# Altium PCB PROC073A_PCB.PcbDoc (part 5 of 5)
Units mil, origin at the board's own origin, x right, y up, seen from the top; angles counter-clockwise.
Board outline 2165.35 x 2165.35 mil, 6 copper layers (Top Layer, L2, L3, L4, L5, Bottom Layer), stack 55.77 mil thick; 284 components, 233 nets, 945 pads, 1419 vias.
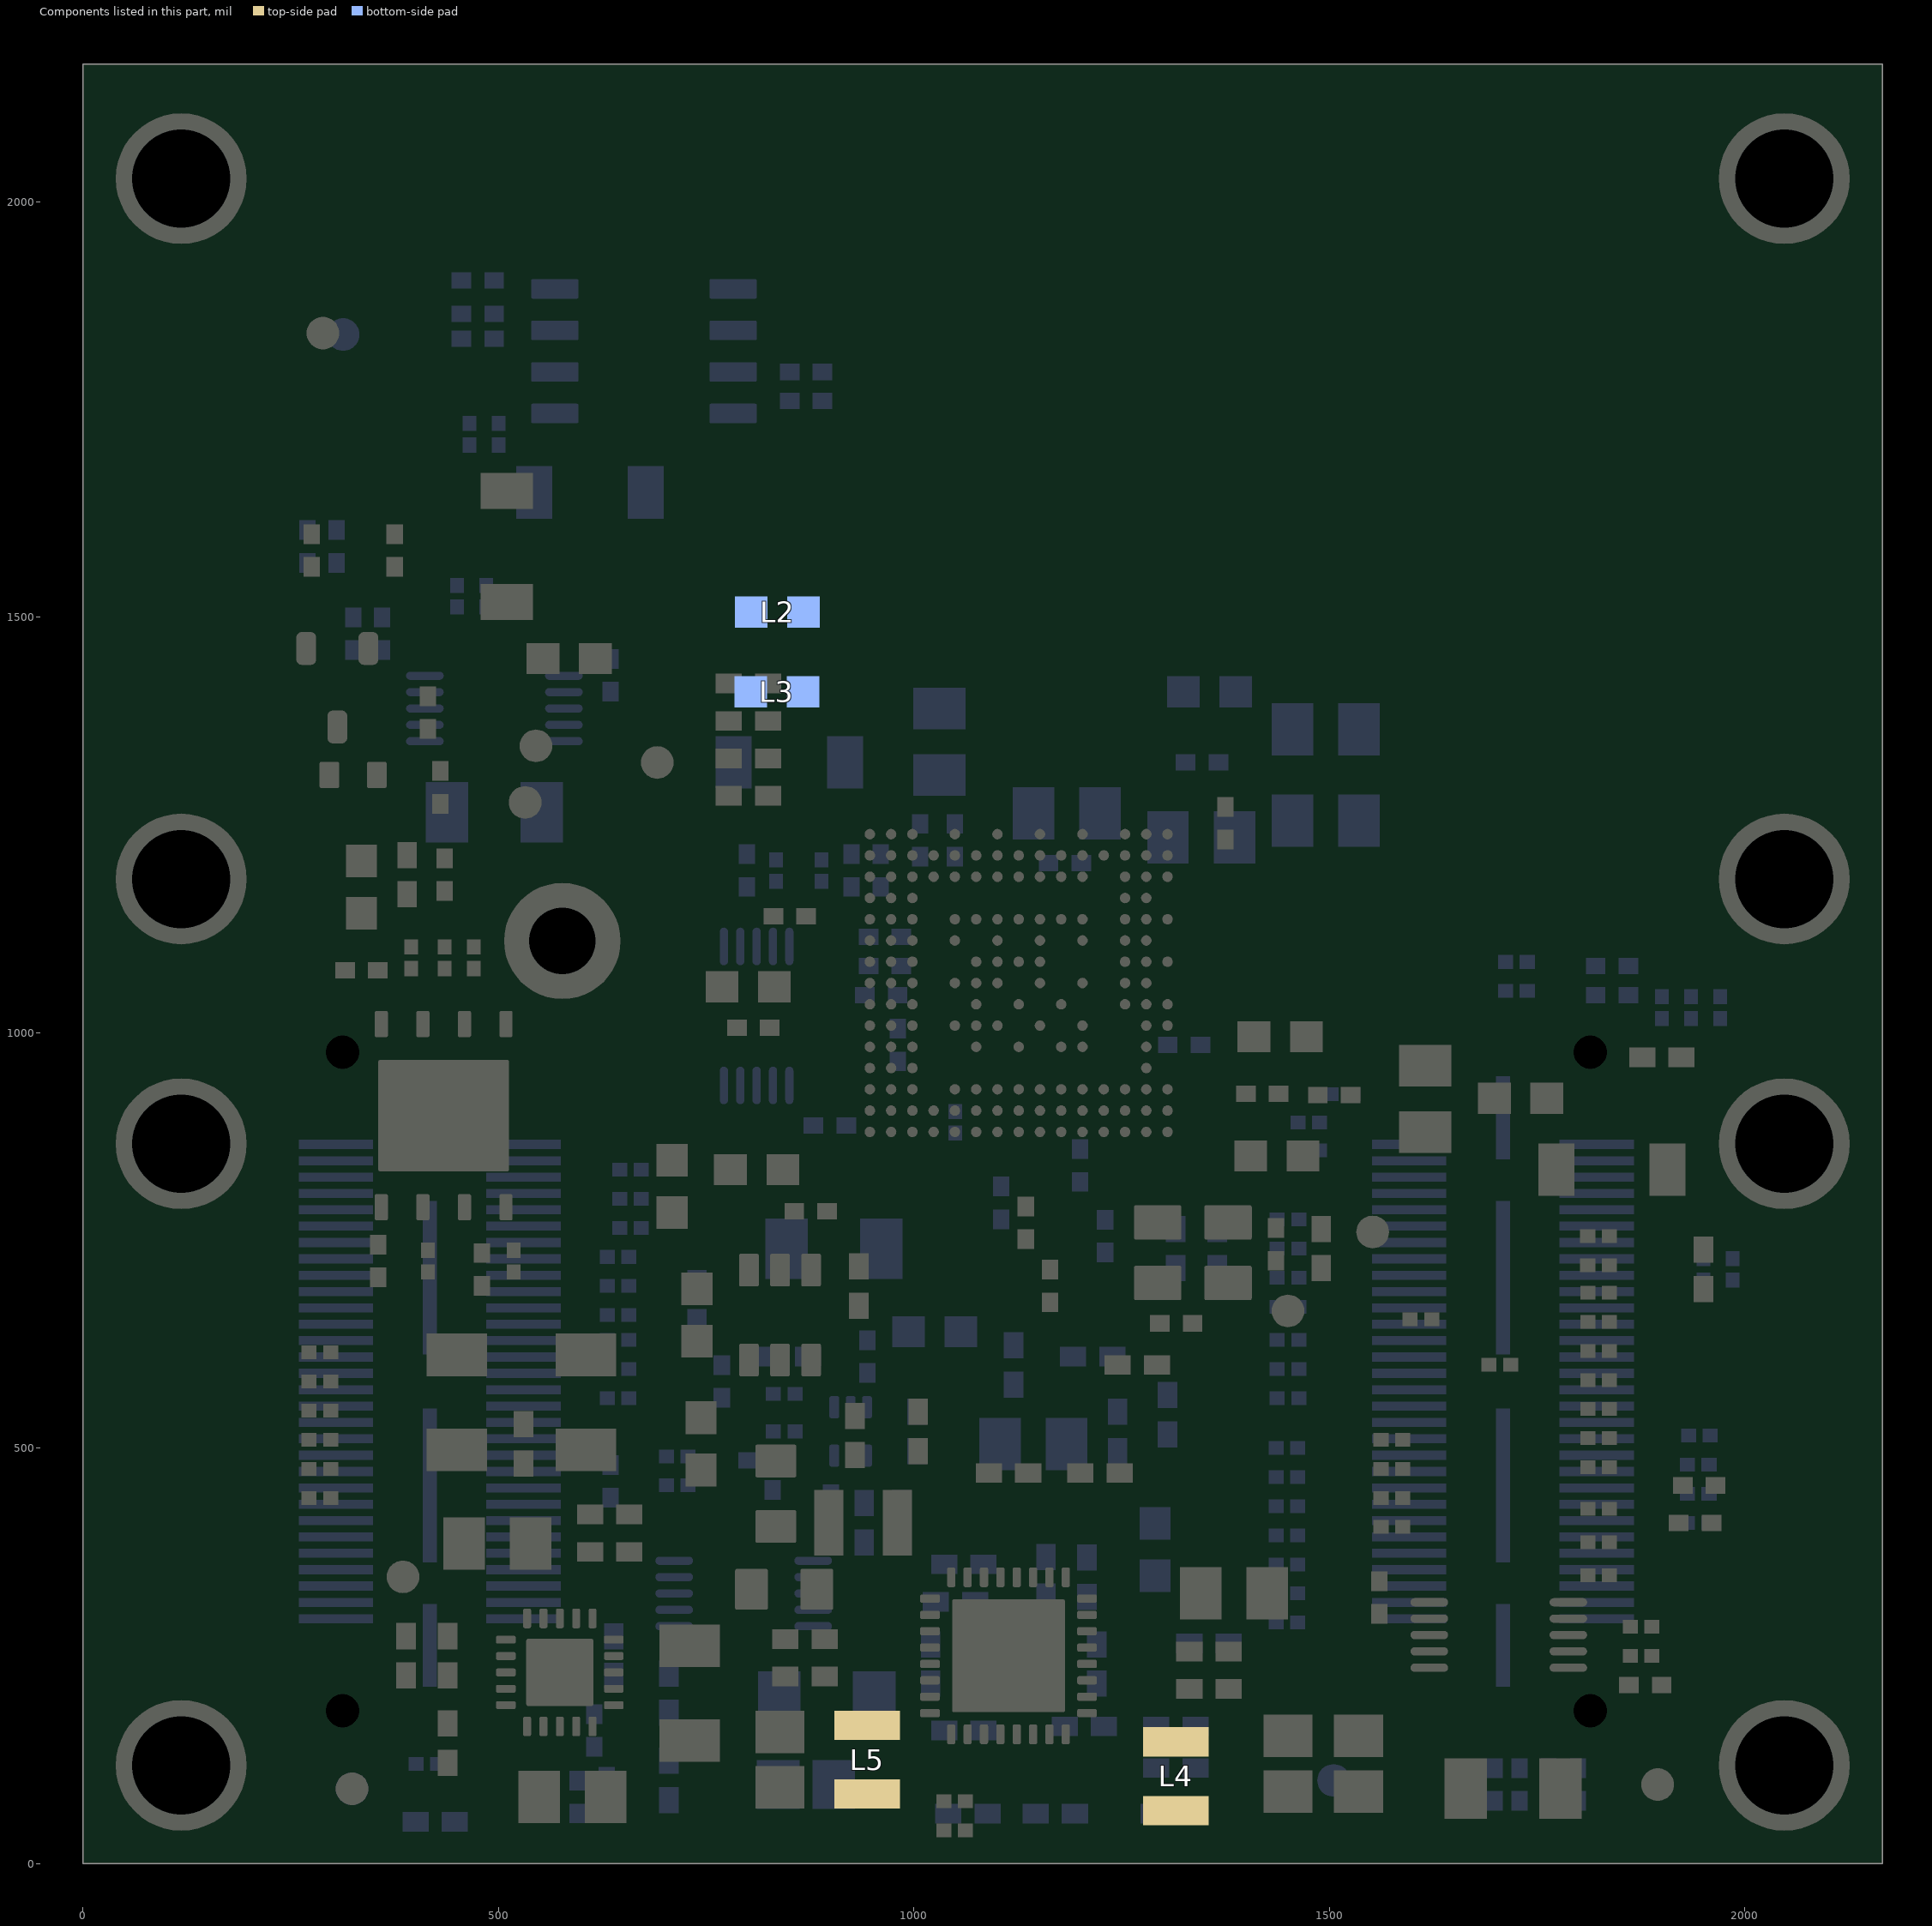
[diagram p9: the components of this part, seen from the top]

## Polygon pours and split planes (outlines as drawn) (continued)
GND on Bottom Layer "TOP-No Net 1" (solid, remove dead copper, pour order 388): 40 vertices, not listed, extent 1067,966 2136,1966
no net on Bottom Solder "RADAR_1V8_L01_P-001" (solid): 34 vertices, not listed, extent 1068,974 1955,2010.87
no net on Top Solder "Top Solder-No Net" (solid): 91 vertices, not listed, extent 801.83,1018 1994,2144
GND on L5 "TOP-No Net 1" (solid, remove dead copper, pour order 376): 32.89,2147.39 2147.89,2147.38 2147.89,23.38 32.89,23.38
GND on L2 "GND_L02_P226" (hatched 90Degree grid 5 track 8, remove dead copper, pour order 226): 35,2140 2135.01,2140 2135,25 34.99,25

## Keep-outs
L2:
  circle w1: c1074.8,1213.16 r7.87
  circle w1: c1177.16,1213.16 r7.87
  circle w1: c1125.98,1213.16 r7.87
  circle w1: c1279.52,1059.62 r7.87
  circle w1: c1279.52,1161.98 r7.87
  circle w1: c1279.52,1110.8 r7.87
  circle w1: c312.12,976.26 r32
  circle w1: c1023.62,1213.16 r7.87
L3:
  circle w1: c312.12,976.26 r32
L4:
  circle w1: c312.12,976.26 r32
L5:
  circle w1: c312.12,976.26 r32
Bottom Layer:
  circle w1: c312.12,976.26 r27.7
Keep-Out Layer:
  circle w1: c1813.86,976.26 r32
  circle w1: c1813.86,183.74 r31
  circle w1: c312.12,183.74 r32
  lines w10: 0,0 0,2165.35 2165.35,2165.35 2165.35,0 0,0
  text ".Layer_Name" at -423,-1858.49 h60

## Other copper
Top Layer:
  pour cut-out: 1039.36,1213.16 cw(c1023.62,1213.16) 1023.62,1197.42 cw(c1023.62,1213.16) 1007.88,1213.16 cw(c1023.62,1213.16) 1023.62,1228.9 cw(c1023.62,1213.16)
  pour cut-out: 1090.54,1213.16 cw(c1074.8,1213.16) 1074.8,1197.42 cw(c1074.8,1213.16) 1059.06,1213.16 cw(c1074.8,1213.16) 1074.8,1228.9 cw(c1074.8,1213.16)
  pour cut-out: 1141.72,1213.16 cw(c1125.98,1213.16) 1125.98,1197.42 cw(c1125.98,1213.16) 1110.24,1213.16 cw(c1125.98,1213.16) 1125.98,1228.9 cw(c1125.98,1213.16)
  pour cut-out: 1192.9,1213.16 cw(c1177.16,1213.16) 1177.16,1197.42 cw(c1177.16,1213.16) 1161.42,1213.16 cw(c1177.16,1213.16) 1177.16,1228.9 cw(c1177.16,1213.16)
  pour cut-out: 1295.26,1161.98 cw(c1279.52,1161.98) 1279.52,1146.24 cw(c1279.52,1161.98) 1263.78,1161.98 cw(c1279.52,1161.98) 1279.52,1177.72 cw(c1279.52,1161.98)
  pour cut-out: 1295.26,1110.8 cw(c1279.52,1110.8) 1279.52,1095.06 cw(c1279.52,1110.8) 1263.78,1110.8 cw(c1279.52,1110.8) 1279.52,1126.54 cw(c1279.52,1110.8)
  pour cut-out: 1295.26,1059.62 cw(c1279.52,1059.62) 1279.52,1043.88 cw(c1279.52,1059.62) 1263.78,1059.62 cw(c1279.52,1059.62) 1279.52,1075.36 cw(c1279.52,1059.62)
  text ".Layer_Name" at -423,-1858.49 h60
L2:
  pour cut-out: 1266.57,249.91 1266.57,264.58 1268.2,266.21 1277.24,266.21 1281.41,262.04 1281.41,246.12 1269.64,246.12 1266.57,249.19 1266.39,249.19
  pour cut-out: 1733.71,281.38 1733.71,296.05 1735.34,297.68 1744.38,297.68 1748.55,293.51 1748.55,277.59 1736.78,277.59 1733.71,280.66 1733.53,280.66
  pour cut-out: 1267.4,288.87 1267.4,303.54 1269.03,305.17 1278.07,305.17 1282.24,301 1282.24,285.08 1270.47,285.08 1267.4,288.15 1267.22,288.15
  pour cut-out: 1366.38,480.03 1381.05,480.03 1382.68,478.4 1382.68,469.36 1378.51,465.19 1362.59,465.19 1362.59,476.96 1365.66,480.03 1365.66,480.21
  pour cut-out: 2140.93,1364.44 1997.92,1364.44 1885.11,1251.63 1885.11,1223.22 1682.7,1020.81 1621.63,1020.81 1392.37,1020.81 1354.68,983.12 1354.68,905.79 1354.68,819.37 1374.9,819.37 1374.9,930.19 1374.9,972.62 1400.28,998 1691.88,998 1908.35,1214.47 1908.35,1239.56 2011.45,1342.66 2140.93,1342.66
  pour cut-out: 1236.78,839.76 1245.87,848.86 1245.87,861.13 1075.37,1031.63 1075.37,1053.79 1033,1096.16 1033,1145.42 1014.95,1163.47 977.13,1201.29 977.13,1273.51 809.63,1441.01 809.63,2144.85 788,2144.85 788,1430.4 956.28,1262.12 956.28,1189.05 1012.83,1132.5 1012.83,1082.88 1057.82,1037.89 1057.82,1018.72
  pour cut-out: 1250,823 1236,809 1236,680 1257,659 1257,621 1263,615 1320,615 1344,639 1403,639 1411,647 1411,672 1433,694 1462,694 1470,702 1470,779 1435,814 1373,814 1373,833 1454.66,833 1486.15,801.5 1486.15,697.29 1465.09,676.23 1444.23,676.23 1426,658 1426,650 1397,621 1354.51,621.01 1329.44,595.94 1257.05,595.94 1236.03,616.97 1236.02,657.78 1216.02,677.8 1216.02,819 1230.01,832.99 1249.76,833
  pour cut-out: 1218.81,673.89 1218.81,658.1 1213.48,652.77 1221.37,644.88 1227.89,644.88 1227.89,650.21 1236.96,659.29 1224.73,671.52 1224.73,673.3
  pour cut-out: 1029,1161 1044,1161 1044,1145.76 1041.24,1143 1023,1143 1023,1155
  pour cut-out: 1060,977.16 1075,977.16 1075,961.93 1072.23,959.16 1054,959.16 1054,971.16
  pour cut-out: 1085.74,975.16 1100.74,975.16 1100.74,959.93 1097.97,957.16 1079.74,957.16 1079.74,969.16
  pour cut-out: 1255,995.16 1270,995.16 1270,979.93 1267.23,977.16 1249,977.16 1249,989.16
  pour cut-out: 1023.84,1035.75 1023.84,1050.75 1039.07,1050.75 1041.84,1047.98 1041.84,1029.75 1029.84,1029.75
  pour cut-out: 1031,1101.16 1046,1101.16 1046,1085.93 1043.23,1083.16 1025,1083.16 1025,1095.16
  pour cut-out: 885,1031.35 900,1031.35 900,1016.11 897.23,1013.35 879,1013.35 879,1025.35
  pour cut-out: 1158.84,1148 1158.84,1163 1174.07,1163 1176.84,1160.23 1176.84,1142 1164.84,1142
  pour cut-out: 1031.49,1213.16 cw(c1023.62,1213.16) 1023.62,1205.29 cw(c1023.62,1213.16) 1015.75,1213.16 cw(c1023.62,1213.16) 1023.62,1221.03 cw(c1023.62,1213.16)
  pour cut-out: 1031.49,1213.16 cw(c1023.62,1213.16) 1023.62,1205.29 cw(c1023.62,1213.16) 1015.75,1213.16 cw(c1023.62,1213.16) 1023.62,1221.03 cw(c1023.62,1213.16)
  text "Layer 2 - GND1" at -403.92,-1847.45 h60
L3:
  pour cut-out: 1267.67,271.41 1276.33,271.41 1287.55,260.19 1287.55,255.38 1277.61,245.44 1266.39,245.44 1261.58,250.25 1261.58,264.68 1267.03,270.13
  pour cut-out: 1180.53,1165.47 1183,1163 1178.14,1158.14 1178.14,1144.86 1173.94,1140.67 1154.33,1140.67 1146.87,1148.13 1146.87,1154.07 1158.27,1165.47
  text "Layer 3 - Sig1" at -394.11,-1858.93 h60
L4:
  text "Layer 4 - Sig2" at -362.17,-1856.02 h60
L5:
  pour cut-out: 885.48,638.59 885.48,641.16 891.89,647.57 897.35,647.57 906.33,638.59 898.95,631.21 898.95,628.33 895.1,628.33 886.44,636.99
  pour cut-out: 1743.38,408.24 1743.38,410.81 1749.79,417.22 1755.25,417.22 1764.23,408.24 1756.85,400.86 1756.85,397.98 1753,397.98 1744.34,406.64
  pour cut-out: 1273.11,265.63 1275.68,265.63 1282.09,259.22 1282.09,253.76 1273.11,244.78 1265.73,252.16 1262.85,252.16 1262.85,256.01 1271.51,264.67
  pour cut-out: 1048,981.06 1021.98,981.06 1021.98,998.59 1048,998.59
  pour cut-out: 1048.65,1032.26 1022.63,1032.26 1022.63,1049.79 1048.65,1049.79
  pour cut-out: 1022.8,1103.52 1048.81,1103.52 1048.81,1085.98 1022.8,1085.98
  pour cut-out: 1180.98,1144 1154.96,1144 1154.96,1161.54 1180.98,1161.54
  pour cut-out: 1064,979 1080,963 1080,959 1071,950 1068,950 1052,966 1052,973 1059,980 1062,980
  text "Layer 5 - GND2" at -367.98,-1863.28 h60
Bottom Layer:
  pour cut-out: 263,1913 317,1967 880,1967 908,1939 908,1877 893,1862 274,1862 263,1873
  text ".Layer_Name" at -423,-1858.49 h60
Multi-Layer:
  pour cut-out: 30,20.18 2140,20.17 2140,2144 30,2144 29.99,0 0,0 0,2165.36 2165.35,2165.35 2165.35,0.17 29.99,0.18

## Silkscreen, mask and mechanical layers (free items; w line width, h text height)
Top Overlay:
  lines w6: 200,430 200,485 ; 205,655 205,570 ; 220,215 275,215 280,220 355,220 ; 280,740 335,740 ; 390,1055 495,1055 495,1125 ; 504,1056 510,1050 510,1064 504,1058 520,1058 586,992 ; 505,1169 480,1144 449,1144 ; 585,905 695,905 695,980 ; 603.73,1591.72 603.73,1733.73 ; 604.41,1591.72 684.68,1591.72 ; 634.5,1588.26 758.59,1464.17 758.59,1447.76 ; 695.62,1610.39 695.62,1736 ; 745,320 775,320 ; 885,745 898,758 953,758 960,765 ; 1272,660 1220,660 1175,615 ; 1449.13,704.85 1502.04,651.94 1502.04,627.08 ; 1540,30 1430,30 ; 1670.06,367.05 1778.21,367.05 1789.85,355.41 ; 1754.39,630.84 1765.27,630.84 1785.4,650.97 1790.58,650.97 ; 1776.26,518.81 1789.21,505.86 ; 1856.87,621.93 1866.52,621.93 ; 1858.13,546.96 1865.57,554.4 1920.49,554.4 ; 1859.42,577.37 1865.9,583.85 1922.43,583.85 ; 1903.1,257.37 1910.87,265.14 1910.87,283.26 1930.93,303.32 1970.26,303.32 ; 1916.39,197.29 1926.83,197.29 ; 200,485 205,480 195,480 200,485 ; 205,570 215,580 195,580 205,570 ; 335,740 330,745 330,735 335,740 ; 355,220 345,210 345,230 355,220 ; 449,1144 454,1139 454,1149 449,1144 ; 586,992 585,993 586,992 ; 775,320 770,315 770,325 775,320 ; 1175,615 1185,615 1175,625 1175,615 ; 1430,30 1435,25 1435,35 1430,30
  text "IWR6843ISK" at 253,1972 h40
  text "PROC073    REV A" at 411.5,1938.01 h45
  text ".Layer_Name" at -423,-1858.49 h60
Bottom Overlay:
  circle w6: c293.4,1360.46 r30
  circle w6: c667.74,914.51 r30
  circle w6: c696.91,1255.44 r30
  circle w6: c1147.51,1381.97 r30
  lines w6: 230.93,827.43 249.25,845.75 ; 251.5,1675.94 251.5,1629.19 255.51,1625.17 ; 261.52,1325.38 348.31,1325.38 348.31,1253.11 359.85,1241.57 359.85,1201.73 359.85,1189.06 406.41,1189.06 406.41,1035.98 ; 271,130 285,144 368,144 380,132 ; 405,1686 445,1686 ; 570.74,24.05 577.73,24.05 593.5,39.82 ; 618.56,537.27 677.15,537.27 677.71,537.83 677.71,732.95 698.6,753.84 698.6,860.37 638.79,860.37 ; 700.64,418.92 719.75,438.04 ; 722.34,1233.17 734.1,1221.41 775.46,1221.41 ; 735.74,562.54 746.02,562.54 ; 767.46,493.87 781.15,480.18 ; 779.7,1163.82 779.7,1235.01 949.23,1235.01 983.54,1269.33 1073.68,1269.33 1073.68,1198.14 1062.42,1186.87 997.88,1186.87 ; 786,528 798,516 813,516 ; 788.84,619.17 788.84,590.22 806.86,572.2 815.21,572.2 ; 792.72,445.07 810.38,445.07 ; 911.78,1082.13 925.28,1082.13 ; 917.3,320.25 917.3,357.3 ; 921.79,570.11 924.97,573.29 924.97,642.14 ; 948.09,650.49 948.09,664.06 961.8,677.77 999.23,677.77 1019.59,698.13 ; 962.33,115.79 962.33,139.57 ; 1014.23,435.32 1028.9,435.32 ; 1078.15,1437.65 1078.15,1512.5 1299.27,1512.5 1299.27,1451.97 ; 1085.69,1414.62 1258.93,1414.62 ; 1144.82,653.19 1156.77,665.14 ; 1149,232.7 1149,243.96 ; 1232.5,108.6 1232.5,136.8 ; 1247.75,215.77 1259.92,227.94 1302.34,227.94 ; 1259.57,636.59 1259.57,663.34 ; 1269.53,575.07 1275.5,581.04 1275.5,613.87 1282.63,621 ; 1283.6,854.36 1283.6,811.31 1300.66,794.25 ; 1320.27,850.1 1320.27,830.93 1355.24,795.96 ; 1402,689 1413,700 ; 1406.22,396.43 1414.27,396.43 ; 1473.61,250.2 1473.61,267.98 ; 1477.01,476.01 1486.26,485.25 1486.26,502.57 ; 1521,1480 1521,1420 ; 1629.96,52.08 1635.91,58.03 1635.91,45.58 1629.41,52.08 1699.48,52.08 ; 1782.9,52.26 1833.77,52.26 1826.03,60 1826.03,45.17 1833.12,52.26 ; 1864.28,1024.13 1864.28,1001.92 1900.82,965.38 ; 1872.86,294.22 1888.58,278.5 1888.54,236.56 ; 1922.17,770.29 1942.88,749.58 ; 1930.65,540.63 1937.25,547.23 1923.77,547.23 1930.65,540.35 1930.65,591.76 ; 1956.58,770.95 1977.95,749.58 ; 445,1686 440,1691 440,1681 445,1686 ; 1521,1420 1511,1430 1531,1430 1521,1420
  text "TEXAS" at 1026,1608 h70
  text "INSTRUMENTS" at 1111,1548 h70
  text "B" at 1159.27,1365.1 h50
  text "A" at 310.33,1344.76 h50
  text "B" at 708.67,1238.57 h50
  text "A" at 684.67,898.81 h50
  text "5V_IN" at 581.26,877.54 h45 r270
  text "60" at 1945,867 h60
  text "5V_IN" at 220.8,864.76 h50 r270
  text "VPP_1P7" at 219.08,671.37 h40 r270
  text "1V8" at 1546.29,359.69 h40
  text "1V2" at 1546.95,328.54 h40
  text "3V3" at 1939.64,309.24 h40
  text "1V0" at 1545.43,290.64 h40
  text "60" at 248,252 h60
  text "5V_IN" at 1964.35,203.39 h40
  text "1" at 1549.43,167.64 h60
  text ".Layer_Name" at -423,-1858.49 h60
Top Paste:
  text ".Layer_Name" at -423,-1858.49 h60
Bottom Paste:
  text ".Layer_Name" at -423,-1858.49 h60
Top Solder:
  rectangle: 33,2005 900,2144
  region: 30,20.18 214.97,20.18 214.97,190.03 170.99,234.01 170.99,645.99 226.41,701.41 226.41,971.41 226.41,2144 30,2144
  region: 1965,20 2140,20.17 2140,2144 1960,2144 1960,815 2015,760 2015,245 1950,180 1950,30 1960,20
  text ".Layer_Name" at -423,-1858.49 h60
  text ".Layer_Name" at -423,-1858.49 h60
Bottom Solder:
  region: 1965,20 2140,20.17 2140,2144 30,2144 30,20.18 214.94,20.18 215.12,189.87 170,234.99 170,644 205,679 205,1113 241,1149 241,1891.29 335.84,1986.13 1940,1986.13 1940,1219 2019.99,1139 2020,970.99 1962.25,913.25 1962.25,827.4 2015.39,774.26 2015.39,235.39 1950,170 1950,35
  region: 1911.1,1225.53 1937.91,1225.53 2022.09,1141.35 2022.09,1135.02 2021.72,1134.65 1931.58,1134.65 1902.9,1163.33 1902.9,1217.7 1911.1,1225.9
  text ".Layer_Name" at -423,-1858.49 h60
Drill Guide:
  text ".Layer_Name" at -423,-1858.49 h60
M1 Board Outline:
  the board outline again, w8
  text ".Layer_Name" at -423,-1858.49 h60
M2 Board Dimensions:
  rectangle: -1000,-1275 -875,-1150
  rectangle: -875,-1400 -500,-1275
  lines w7: -1000,-1275 0,-1275 ; -875,-1400 -875,-1150 ; -750,-1400 -750,-1150 ; -500,-1400 -500,-1150 ; -250,-1400 -250,-1150 ; -1000,-1400 0,-1400 0,-1150 -1000,-1150 -1000,-1400
M3 3D STEP Top:
  text ".Layer_Name" at -423,-1858.49 h60
M4 3D STEP Bottom:
  text ".Layer_Name" at -423,-1858.49 h60
M5 Assembly Top:
  circle w15: c344,1478 r3
  lines w6: 380,1130 495,1130 495,1050 385,1050 ; 500,1205 595,1205 595,1285 500,1285 ; 535,1205 470,1140 ; 470,1140 480,1140 470,1150 470,1140
  lines w10: -1292,-1930.17 5308,-1930.17 ; -1292,-1726.83 5310,-1726.83 ; -1292,-1523.5 -1292,-2133.5 2713,-2133.5 5310,-2133.5 5310,-1523.5 -1291.5,-1523.5 -1291.5,-2133.5 284,-2133.5 ; 1173,-2133.5 1173,-1523.5 ; 2440,-1726.83 2440,-1523.5 ; 3280,-1726.83 3280,-1523.5 ; 3902,-2140 3902,-1937.17
  text "COMPONENTS MARKED 'DNP' SHOULD NOT BE POPULATED." at 153.5,-1318.5 h60
  text "ASSEMBLY VARIANT:" at 153,-1434 h60
  text ".VariantName" at 1189,-1434 h60
  text "PCB VIEWED FROM TOP SIDE" at -1228.5,-1655.67 h60
  text "BOARD #:" at 1248,-1655.67 h60
  text ".PRJ_Number" at 1793.5,-1655.67 h60
  text "REV:" at 2638,-1655.67 h60
  text ".PCB_Rev" at 2929.5,-1655.67 h60
  text "SVN REV:" at 3476,-1655.67 h60
  text ".VersionControl_RevNumber" at 3982,-1655.67 h60
  text "Assembly Layer Top" at -433,-1855 h60
  text "TID #:" at 1248,-1859 h60
  text ".TID" at 1793.5,-1859 h60
  text "PLOT NAME =" at -1228.5,-2064.34 h60
  text ".plot_File_Name" at -423,-2064.34 h60
  text "GENERATED    :" at 1250,-2064.34 h60
  text ".Print_Date" at 2119.5,-2064.34 h60
  text ".Print_Time" at 2848.5,-2064.34 h60
  text "TEXAS INSTRUMENTS" at 4113,-2064.34 h60
M6 Assembly Bottom:
  lines w6: 705,725 705,865 ; 786.98,637.71 791.01,633.68 791.01,583.68 810.46,564.23 810.46,571.43 802.41,563.38 809.61,563.38 ; 833.84,1230.77 833.84,1248.26 ; 1770.26,1133.61 1770.26,1075.96 1798.64,1047.57 1798.64,1057.45 1788.68,1047.48 1796.09,1047.48 ; 705,865 714.25,855.75 695.75,855.75 705,865
  lines w10: -1292.5,-1727.33 5309.5,-1727.33 ; -1290.5,-1930.67 5309.5,-1930.67 ; 115.5,-2140.5 115.5,-1937.67 ; 737.5,-1727.33 737.5,-1524 ; 1577.5,-1727.33 1577.5,-1524 ; 2844.5,-2134 2844.5,-1524 ; 3733.5,-2134 5309,-2134 5309,-1524 -1292.5,-1524 -1292.5,-2134 1304.5,-2134 5309.5,-2134 5309.5,-1524
  text "2" at 323,868 h45
  text "1" at 532,868 h45
  text "59" at 1636,865.43 h45
  text "60" at 1821.54,865.43 h45
  text "60" at 345,266 h45
  text "59" at 533,266 h45
  text "1" at 1611,265 h45
  text "2" at 1822,265 h45
  text "COMPONENTS MARKED 'DNP' SHOULD NOT BE POPULATED." at 5102,-1318 h60
  text ".VariantName" at 4058,-1434 h60
  text "ASSEMBLY VARIANT:" at 5097,-1434 h60
  text ".VersionControl_RevNumber" at 35.5,-1656.17 h60
  text "SVN REV:" at 541.5,-1656.17 h60
  text ".PCB_Rev" at 1088,-1656.17 h60
  text "REV:" at 1379.5,-1656.17 h60
  text ".PRJ_Number" at 2224,-1656.17 h60
  text "BOARD #:" at 2769.5,-1656.17 h60
  text "PCB VIEWED FROM BOTTOM SIDE" at 5246,-1656.17 h60
  text "Assembly Bottom Layer" at 4885,-1845 h60
  text ".TID" at 2224,-1859.5 h60
  text "TID #:" at 2769.5,-1859.5 h60
  text "TEXAS INSTRUMENTS" at -95.5,-2064.84 h60
  text ".Print_Time" at 1169,-2064.84 h60
  text ".Print_Date" at 1898,-2064.84 h60
  text "GENERATED    :" at 2767.5,-2064.84 h60
  text ".plot_File_Name" at 4440.5,-2064.84 h60
  text "PLOT NAME =" at 5246,-2064.84 h60
M7 LPKF Text Top:
  lines w2: 1007.88,1213.16 1039.36,1213.16 ; 1015.75,1213.16 1031.49,1213.16 ; 1023.62,1197.42 1023.62,1228.9 ; 1023.62,1205.29 1023.62,1221.03
M9 Title Sheet:
  drawing of 57 lines, arcs and shapes, not listed
  text "1" at -260.16,7036.5 h70
  text "2" at 2235.5,7036.5 h70
  text "3" at 4724.84,7036.5 h70
  text "4" at 7231.51,7036.5 h70
  text "5" at 9730.5,7036.5 h70
  text "6" at 12235.5,7036.5 h70
  text "A" at -1416.5,5893.5 h70
  text "A" at 13383.5,5893.5 h70
  text "B" at -1416.5,3513.5 h70
  text "B" at 13383.5,3513.5 h70
  text "C" at -1416.5,1138.5 h70
  text "C" at 13383.5,1138.5 h70
  text "PROJECT TITLE:" at 10343.5,-722.5 h45
  text ".PRJ_Title" at 10393.5,-855.83 h70
  text "DESIGNED FOR:" at 10343.5,-1023.5 h45
  text ".PRJ_Customer" at 10393.5,-1163.5 h70
  text "D" at -1416.5,-1231.5 h70
  text "D" at 13383.5,-1231.5 h70
  text "FILE NAME:" at 10343.5,-1323.5 h45
  text ".PCB_File_Name_No_Path" at 10393.5,-1443.5 h70
  text "Texas Instruments (TI) and/or its licensors do not warrant the accuracy or completeness of this specification" at 5374,-1605.34 h45
  text "ENGINEER:" at 10343.5,-1613.5 h45
  text "LAYOUT BY:" at 11848.5,-1613.5 h45
  text "or any information contained therein. TI and/or its licensors do not warrant that this design will meet" at 5329.01,-1718 h45
  text ".PRJ_Engineer" at 10393.5,-1768.49 h70
  text ".PCB_Layout" at 11899,-1768.49 h70
  text "the specifications, will be suitable for your application or fit for any particular purpose, or will operate in" at 5329.01,-1830.67 h45
  text "ALTIUM DESIGNER VERSION:" at 11848.5,-1923.5 h45
  text "an implementation. TI and/or its licensors do not warrant that the design is production worthy. You should" at 5329.01,-1943.33 h45
  text "completely validate and test your design implementation to confirm the system functionality for your application." at 5374,-2056 h45
  text ".print_Scale" at 10393.5,-2056.83 h70
  text ".Application_BuildNumber" at 11899,-2056.83 h70
  text "1" at -260.16,-2263.5 h70
  text "2" at 2235.5,-2263.5 h70
  text "3" at 4724.84,-2263.5 h70
  text "4" at 7231.51,-2263.5 h70
  text "5" at 9730.5,-2263.5 h70
  text "6" at 12235.5,-2263.5 h70
M10 Fab Notes:
  drawing of 189 lines, arcs and shapes, not listed
  text "DESIGN INFORMATION" at 11382.02,5356.17 h60
  text "MIN. TRACK WIDTH:" at 10737.46,5224.05 h60
  text "4" at 11833.7,5224.05 h60
  text "MIL" at 11988.46,5224.05 h60
  text "MIN. CLEARANCE:" at 10737.46,5099.92 h60
  text "4" at 11773.7,5099.93 h60
  text "MIL" at 11988.46,5099.92 h60
  text "MIN. VIA PAD SIZE:" at 10737.46,4975.8 h60
  text "13.77" at 11679,4971 h60
  text "MIL" at 12011,4967 h60
  text "0.099mm (3.9MIL)" at 11432.46,4845.9 h60
  text "EXTERNAL" at 12194,4842 h60
  text "MINIMUM ANNULAR RING" at 10408.23,4837.67 h60
  text "PER" at 10608.23,4727.55 h60
  text "IPC-D-275 CLASS 2 LEVEL C" at 10828.23,4727.54 h60
  text "MIL, HOLES" at 12316.46,4627.07 h60
  text "+/-" at 11924,4618.48 h60
  text "+/-" at 12778,4618.48 h60
  text "REGISTRATION TOLERANCES:" at 10408.23,4617.42 h60
  text "METAL" at 11608,4617.42 h60
  text "5" at 12184.2,4617.42 h60
  text "3" at 13017.2,4617.42 h60
  text "MIL" at 13133.46,4617.42 h60
  text "HOLE SIZE TOLERANCE (UNLESS OTHERWISE SPECIFIED):" at 10408.23,4519.1 h60
  text "+/-" at 12778,4516.23 h60
  text "3" at 13017.2,4515.17 h60
  text "MIL" at 13133.46,4515.17 h60
  text "MATERIAL:" at 10333.46,4377.52 h60
  text "FR-4 High Tg" at 11319.9,4249 h60
  text "X" at 12062,4244 h60
  text "FR-408" at 10754.46,4236.49 h60
  text "OTHER" at 12242.46,4236.49 h60
  text "X" at 12233,4096.01 h60
  text "62 MIL (1.6mm) +/-10%" at 11074.56,4093.46 h60
  text "57.37 MIL +/-10%" at 12655,4087 h45
  text "THICKNESS:" at 10408.23,4085.24 h60
  text "OTHER" at 12359.46,4085.24 h60
  text "TOLERANCE:" at 10408.23,3946.92 h60
  text "X" at 11256.46,3946.92 h60
  text "ANSI IPC-6012 TYPE 3 CLASS 2" at 11434.48,3946.92 h60
  text "OTHER +/-" at 11434.46,3802.73 h60
  text "BOW & TWIST:" at 10408.23,3657.54 h60
  text "X" at 11256.46,3657.54 h60
  text "ANSI IPC-6012 TYPE 3 CLASS 2" at 11434.48,3657.54 h60
  text "OTHER +/-" at 11434.46,3510.85 h60
  text "DRILLING:" at 10333.46,3380.23 h60
  text "NC_DRILL FILES" at 12094.46,3275.04 h60
  text "REFERENCE:" at 10408.23,3271.1 h60
  text "X" at 11065.46,3271.01 h60
  text "AS SHOWN" at 11243.46,3271.1 h60
  text "X" at 11966.46,3271.1 h60
  text "OTHER" at 12392.46,3128.85 h60
  text "PTH COPPER THICKNESS:" at 10407.91,3125.32 h60
  text "X" at 11547.14,3125.32 h60
  text "20-30 um" at 11675.14,3125.32 h60
  text "BOARD FINISH:" at 10333.46,2977.73 h60
  text "SILKSCREEN:" at 10488.68,2867.6 h60
  text "X" at 11446.46,2867.6 h60
  text "TOP" at 11563.46,2867.6 h60
  text "X" at 11956.46,2867.6 h60
  text "BOTTOM" at 12074.46,2867.6 h60
  text "SILKSCREEN COLOR:" at 10488.68,2712.41 h60
  text "X" at 11445.46,2712.41 h60
  text "WHITE" at 11563.46,2712.41 h60
  text "OTHER" at 12074.46,2712.41 h60
  text "GREEN" at 11694.46,2568.96 h60
  text "X" at 12168.46,2568.96 h60
  text "OTHER" at 12312.46,2568.96 h60
  text "RED" at 12685,2568.96 h60
  text "SOLDER RESIST COLOR:" at 10488.68,2562.1 h60
  text "NOTES:" at 3613.12,2512.94 h60
  text "MATTE" at 11694.46,2414.71 h60
  text "SEMI-GLOSS" at 12312,2414.07 h60
  text "1. THIS IS AN IMPEDANCE CONTROL BOARD" at 3627.14,2338.63 h60
  text "IMMERSION GOLD (ENIG)" at 11394.46,2241.94 h60
  text "ENEPIG" at 12732,2234.72 h60
  text "SURFACE FINISH:" at 10333.46,2233.72 h60
  text "2. VIA'S ON PAD AND BGA PACKAGE AREA SHOULD BE FILLED WITH CONDUCTIVE MATERIAL AND SURFACE SHOULD BE FLAT" at 3605.12,2167.94 h60
  text "IMM. TIN/SILVER OR EQUIV" at 10663,2096.4 h60
  text "X" at 10510,2093.72 h60
  text "OTHER" at 12094.46,2092.47 h60
  text "BGA AREA VIAS SHOULD BE CAPPED WITH COPPER PLATING TO ENSURE FLAT SURFACE" at 3765.12,2021.94 h60
  text "ARRAY/PANEL:" at 10333.46,1937.09 h60
  text "CUT AND TRIM PER M1 BOARD OUTLINE" at 11394.46,1928.87 h60
  text "FLATNESS TOLERANCE FOR VIA ON PADS: +0.000 /- 0.001 INCHES ON BOTH SIDES." at 3768,1910 h60
  text "N.C. ROUTE" at 11394.46,1792.9 h60
  text "X" at 12082.46,1792.9 h60
  text "V. SCORE" at 12260.46,1792.9 h60
  text "OTHER THAN BGA  AND VIA'S ON THE PAD VIA FILLING REQUIREMENT CAN BE EXMPTED" at 3760,1768 h60
  text "CERTIFICATION:" at 10333.46,1663.77 h60
  text "MATERIALS AND WORKMANSHIP FOR ALL PCBS" at 11058.46,1663.77 h60
  text "3.  SOLDER MASK OPENING IS KEPT SAME SIZE AS PAD (1:1)" at 3564.12,1622.94 h60
  text "TO MEET OR EXCEED THE REQUIREMENTS OF:" at 11058.46,1569.71 h60
  text "THE MANUFACTURER IS REQUESTED TO RESIZE IT AS PER THEIR SOLDERMASK TOLERANCE EXCEPT NPTH DRILL AND FIDUCIALS." at 3741.12,1495.94 h60
  text "X" at 10695.97,1441.08 h60
  text "ANSI IPC-A-600F CLASS ->" at 10823.96,1441.08 h60
  text "X" at 12471.97,1441.08 h60
  text "2" at 12581.96,1441.08 h60
  text "1" at 12266.96,1439.58 h60
  text "3" at 12935.96,1439.58 h60
  text "4. VENDOR SHOULD FOLLOW ROHS COMPLIANT PROCESS AND Pb FREE FOR MANUFACTURING" at 3566.12,1375.94 h60
  text "X" at 11507.97,1293.39 h60
  text "RoHS" at 11635.96,1293.39 h60
  text "OTHER" at 12280.36,1293.39 h60
  text "PER ORDER" at 12677.42,1293.39 h60
  text "5.  MANUFACTURER'S IDENTIFICATION,DATECODE LETTER SHALL BE SILKSCREENED ON SOLDER SIDE" at 3566.12,1215.94 h60
  text "ALL BOARDS MUST MEET OR EXCEED UL94-V0 REQUIREMENTS." at 10361,1139.57 h60
  text "OF THE BOARD." at 3711.12,1094.94 h60
  text "PCB MUST BEAR THE UL94V-0 UL REGISTERED MATERIAL ID NUMBER" at 10361,1023.5 h60
  text "6.  TRACE WIDTH SHOULD BE ACCURATELY ETCHED. MAX TOLERANCE +/- 1 MIL" at 3552.74,949.98 h60
  text "ADDITIONAL REQUIREMENTS:" at 10333.46,854.08 h60
  text "7.  LAYER TO LAYER REGISTRATION SHALL BE WITHIN +/-2 MIL" at 3555.93,794.83 h60
  text "MICROSECTION:" at 10408.23,746.95 h60
  text "YES" at 11313.96,746.95 h60
  text "8.  REFER IMPEDANCE TABLE FOR IMPEDANCE CONTROL TRACES ON LAYER 1 AND LAYER 6." at 3549.29,649.96 h60
  text "REQUIRED" at 12175.46,602.62 h60
  text "BARE BOARD ELEC. TEST:" at 10408.23,599.76 h60
  text "NONE" at 11713.96,599.76 h60
  text "X" at 12057.46,599.76 h60
  text "PER ORDER" at 12767.46,599.76 h60
  text "10OHM DIFFERENTIAL IMPEDANCE CONTROL TRACES." at 3745.32,532.13 h60
  text "XX MIL VIAS REQUIRE NON-CONDUCTIVE FILL AND PLANARIZE" at 10592,454 h59
  text "9. FOR ACCURACY OF THE ANTENNA DIMENSION, NEED TO BE MEASURE THE  ANTENNA DIMENSIONS ON ONE BAORD" at 3547.29,383.42 h60
  text "XX MIL VIAS REQUIRE CONDUCTIVE FILL AND PLANARIZE" at 10583,295 h60
  text "AS PER  ANTENNA DOCUMENT( Visio-IWR_60GHz4)." at 3690,263 h60
  text "OUTER XX MIL TRACES REQUIRE 50 OHM SINGLE-ENDED IMPEDANCE" at 10578.15,152.1 h58
  text "10.  INTENTIONAL ONE NET ANTENNA VIA IS PRESENT IN DESIGN" at 3539,130 h60
  text "LAYER 1 & 6 (INNER LAYERS) XX MIL WIDE, XX MIL SPACE / TRACES REQUIRE 100 OHM DIFFERENTIAL IMPEDANCE" at 10617,-98 h60
M11 Gerber Information:
  lines w10: -1292,-1930.17 5308,-1930.17 ; -1292,-1726.83 5310,-1726.83 ; -1292,-1523.5 -1292,-2133.5 2713,-2133.5 5310,-2133.5 5310,-1523.5 -1291.5,-1523.5 -1291.5,-2133.5 284,-2133.5 ; 1173,-2133.5 1173,-1523.5 ; 2440,-1726.83 2440,-1523.5 ; 3280,-1726.83 3280,-1523.5 ; 3902,-2140 3902,-1937.17
  text "ALL ARTWORK VIEWED FROM TOP SIDE" at -1228.5,-1655.67 h60
  text "BOARD #:" at 1248,-1655.67 h60
  text ".PRJ_Number" at 1793.5,-1655.67 h60
  text "REV:" at 2638,-1655.67 h60
  text ".PCB_Rev" at 2929.5,-1655.67 h60
  text "SVN REV:" at 3476,-1655.67 h60
  text ".VersionControl_RevNumber" at 3982,-1655.67 h60
  text "LAYER NAME =" at -1228.5,-1858.49 h60
  text "TID #:" at 1248,-1859 h60
  text ".TID" at 1793.5,-1859 h60
  text "PLOT NAME =" at -1228.5,-2064.34 h60
  text ".plot_File_Name" at -423,-2064.34 h60
  text "GENERATED    :" at 1250,-2064.34 h60
  text ".Print_Date" at 2119.5,-2064.34 h60
  text ".Print_Time" at 2848.5,-2064.34 h60
  text "TEXAS INSTRUMENTS" at 4113,-2064.34 h60
M12 Stackup:
  drawing of 428 lines, arcs and shapes, not listed
  text "Layer" at 5209.12,6605.06 h60
  text "Name" at 5619.03,6605.06 h60
  text "Material" at 6548.78,6605.06 h60
  text "Thickness" at 7718.44,6605.06 h60
  text "Constant" at 8368.28,6605.06 h60
  text "Board Layer Stack" at 8938.14,6605.06 h60
  text "1" at 5209.12,6485.06 h60
  text "Top Overlay" at 5619.03,6485.06 h60
  text "2" at 5209.12,6365.06 h60
  text "Top Solder" at 5619.03,6365.06 h60
  text "Solder Resist" at 6548.78,6365.06 h60
  text "0.80mil" at 7718.44,6365.06 h60
  text "1" at 8368.28,6365.06 h60
  text "3" at 5209.12,6245.06 h60
  text "Top Layer" at 5619.03,6245.06 h60
  text "Copper" at 6548.78,6245.06 h60
  text "1.60mil" at 7718.44,6245.06 h60
  text "4" at 5209.12,6125.06 h60
  text "Dielectric 1" at 5619.03,6125.06 h60
  text "RO4835 LOPRO" at 6548.78,6125.06 h60
  text "4.00mil" at 7718.44,6125.06 h60
  text "3.66" at 8368.28,6125.06 h60
  text "5" at 5209.12,6005.06 h60
  text "L2" at 5619.03,6005.06 h60
  text "Copper" at 6548.78,6005.06 h60
  text "1.40mil" at 7718.44,6005.06 h60
  text "6" at 5209.12,5885.06 h60
  text "Dielectric 2" at 5619.03,5885.06 h60
  text "1080 (66)X2  370HR" at 6548.78,5885.06 h60
  text "5.67mil" at 7718.44,5885.06 h60
  text "3.9" at 8368.28,5885.06 h60
  text "7" at 5209.12,5765.06 h60
  text "L3" at 5619.03,5765.06 h60
  text "Copper" at 6548.78,5765.06 h60
  text "1.20mil" at 7718.44,5765.06 h60
  text "8" at 5209.12,5645.06 h60
  text "Dielectric 3" at 5619.03,5645.06 h60
  text "4-7628  370HR" at 6548.78,5645.06 h60
  text "28.00mil" at 7718.44,5645.06 h60
  text "4.36" at 8368.28,5645.06 h60
  text "9" at 5209.12,5525.06 h60
  text "L4" at 5619.03,5525.06 h60
  text "Copper" at 6548.78,5525.06 h60
  text "1.20mil" at 7718.44,5525.06 h60
  text "10" at 5209.12,5405.06 h60
  text "Dielectric 4" at 5619.03,5405.06 h60
  text "1080 (66)X2  370HR" at 6548.78,5405.06 h60
  text "5.90mil" at 7718.44,5405.06 h60
  text "3.9" at 8368.28,5405.06 h60
  text "11" at 5209.12,5285.06 h60
  text "L5" at 5619.03,5285.06 h60
  text "Copper" at 6548.78,5285.06 h60
  text "1.20mil" at 7718.44,5285.06 h60
  text "12" at 5209.12,5165.06 h60
  text "Dielectric 5" at 5619.03,5165.06 h60
  text "1-2166   370HR" at 6548.78,5165.06 h60
  text "4.00mil" at 7718.44,5165.06 h60
  text "4.26" at 8368.28,5165.06 h60
  text "13" at 5209.12,5045.06 h60
  text "Bottom Layer" at 5619.03,5045.06 h60
  text "Copper" at 6548.78,5045.06 h60
  text "1.60mil" at 7718.44,5045.06 h60
  text "14" at 5209.12,4925.06 h60
  text "Bottom Solder" at 5619.03,4925.06 h60
  text "Solder Resist" at 6548.78,4925.06 h60
  text "0.80mil" at 7718.44,4925.06 h60
  text "1" at 8368.28,4925.06 h60
  text "15" at 5209.12,4805.06 h60
  text "Bottom Overlay" at 5619.03,4805.06 h60
  text "IMPEDANCE TABLE" at 5201.51,4284.15 h80
  text "SPACING" at 5830,4084 h70
  text "LAYER" at 5080,4079 h70
  text "TRACE WIDTH" at 5345,4079 h70
  text "IMPEDANCE +/- 10%" at 6165,4079 h70
  text "REFERENCE LAYER" at 6890,4079 h70
  text "TOP" at 5115,3929 h70
  text "7.795 MILS" at 5400,3924 h65
  text "8 MILS" at 5855,3924 h65
  text "50 OHM" at 6275,3924 h65
  text "LAYER-2 (GND LAYER)" at 6840,3924 h65
  text "SPACING" at 5880,3554 h70
  text "LAYER" at 5130,3549 h70
  text "TRACE WIDTH" at 5395,3549 h70
  text "IMPEDANCE +/- 10%" at 6215,3549 h70
  text "REFERENCE LAYER" at 6940,3549 h70
  text "LAYER-2 AND" at 6905,3414 h65
  text "TOP AND" at 5065,3399 h70
  text "5.2 MILS" at 5495,3399 h65
  text "5 MILS" at 5905,3394 h65
  text "100 OHM" at 6340,3394 h65
  text "LAYER-5" at 6920,3339 h65
  text "BOTTOM" at 5085,3329 h60
M13 Component Bodies Top:
  text ".Layer_Name" at -423,-1858.49 h60
M14 Component Bodies Bottom:
  text ".Layer_Name" at -423,-1858.49 h60
M15 Courtyards Top:
  text ".Layer_Name" at -423,-1858.49 h60
M16 Courtyards Bottom:
  text "NOTES: UNLESS OTHERWISE SPECIFIED." at 4550.94,3572.05 h60
  text "1. FABRICATE PER IPC-6012A CLASS 2." at 4550.94,3418.93 h60
  text "2. FOR BOARD THICKNESS AND IMPEDANCE DETAILS REFER STACKUP DOCUMENT." at 4550.94,3310.05 h60
  text "3. PRINTED WIRING BOARD SHALL COMPLY WITH REQUIREMENTS OF ANSI/J-STD-003." at 4550.94,3193.05 h60
  text "4. SURFACE FINISH:IMMERSION SILVER" at 4550.94,3077.05 h60
  text "5. SOLDERMASK ON BOTH SIDES OF THE BOARD SHALL BE LPI, COLOR RED." at 4550.94,2959.05 h60
  text "6. SILK SCREEN LEGEND TO BE APPLIED PER LAYER STACKUP USING WHITE" at 4550.94,2830.05 h60
  text "NON-CONDUCTIVE EPOXY INK." at 4670.94,2717.05 h60
  text "7. THIS PRINTED WIRING BOARD IS DESIGNED WITH A MINIMUM CONDUCTOR" at 4550.94,2597.05 h60
  text "WIDTH AND SPACING OF 4 MIL &  4 MILS." at 4720.94,2474.05 h60
  text "8. ALL VIAS ARE TENTED ON BOTH SIDES UNLESS SOLDERMASK OPENED IN GERBER." at 4550.94,2360.05 h60
  text "9. ALL VIAS ON PAD INCLUDING BGA AREA SHOULD BE FILLED WITH NON CONDUCTIVE EPOXY AND SURFACE SHOULD BE FLAT" at 4550.94,2211.05 h60
  text "BGA AREA VIAS SHOULD BE CAPPED WITH COPPER PLATING TO ENSURE FLAT SURFACE" at 4720.94,2104.05 h60
  text "REFER VIA FILL DOCUMENT TO IDENTIFY THE VIAS TO BE FILLED" at 4720.94,2000.05 h60
  text "FLATNESS TOLERANCE FOR VIA ON PADS: +0.000 /- 0.001 INCHES ON BOTH SIDES." at 4720.94,1891.05 h60
  text "10. SOLDER MASK OPENING IS KEPT SAME SIZE AS PAD (1:1)" at 4550.94,1771.05 h60
  text "THE MANUFACTURER IS REQUESTED TO RESIZE IT AS PER THEIR SOLDERMASK TOLERANCE EXCEPT NPTH DRILL AND FIDUCIALS." at 4720.94,1669.05 h60
  text "11. VENDOR SHOULD FOLLOW ROHS COMPLIANT PROCESS AND Pb FREE FOR MANUFACTURING" at 4564.94,1564.05 h60
  text "12. MANUFACTURER'S IDENTIFICATION,DATECODE LETTER SHALL BE SILKSCREENED ON SOLDER SIDE" at 4564.94,1439.05 h60
  text "OF THE BOARD." at 4734.94,1326.05 h60
  text "13. TRACE WIDTH SHOULD BE ACCURATELY ETCHED. MAX TOLERANCE +/- 1 MIL" at 4564.94,1212.05 h60
  text "14. BOARD DIMENSIONS ARE IN MM)." at 4564.94,1073.05 h60
  text "15. BOW AND TWIST SHALL NOT EXCEED 0.7% OF LONGEST SIDE" at 4564.94,931.05 h60
  text "16. PCB Material must meet or exceed UL94V-0 requirements." at 4564.94,784.05 h60
  text "PCB must bear the UL94V-0 registered material ID number." at 4734.94,682.05 h60
  text "17. LAYER TO LAYER REGISTRATION SHALL BE WITHIN +/-2 MIL" at 4564.94,542.05 h60
  text "18. REFER STACKUP DOCUMENT FOR IMPEDANCE CONTROL TRACES ON LAYER 1." at 4564.94,404.05 h60
  text "50 OHM SINGLE ENDED AND 10OHM DIFFERENTIAL IMPEDANCE CONTROL TRACES." at 4734.94,305.05 h60
  text ".Layer_Name" at -423,-1858.49 h60
Drill Drawing:
  circle w15: c-574.82,5693.64 r22.1
  circle w15: c-574.82,5693.64 r36.84
  lines w15: -678.96,5441.32 4509.34,5441.32 ; -678.96,6435.88 4509.34,6435.88 ; -554.54,3838.35 4368.53,3838.35 ; -554.54,4004.11 4368.53,4004.11 ; -228.48,5275.56 -228.48,6601.64 ; -104.06,3672.59 -104.06,4169.87 ; 250.07,5275.56 250.07,6601.64 ; 374.49,3672.59 374.49,4169.87 ; 1098.82,5275.56 1098.82,6601.64 ; 1223.24,3672.59 1223.24,4169.87 ; 1444.34,5275.56 1444.34,6601.64 ; 1568.76,3672.59 1568.76,4169.87 ; 1944.55,5275.56 1944.55,6601.64 ; 2068.97,3672.59 2068.97,4169.87 ; 2690.73,5275.56 2690.73,6601.64 ; 2815.15,3672.59 2815.15,4169.87 ; 3493.84,5275.56 3493.84,6601.64 ; 3618.26,3672.59 3618.26,4169.87 ; -678.96,5275.56 4509.34,5275.56 4509.34,6601.64 -678.96,6601.64 -678.96,5275.56 ; -611.65,5491.05 -537.98,5491.05 -537.98,5564.72 -611.65,5564.72 -611.65,5491.05 ; -611.65,5859.4 -574.82,5822.57 -537.98,5859.4 -574.82,5896.24 -611.65,5859.4 ; -611.65,6062 -537.98,6062 -574.82,5988.33 -611.65,6062 ; -611.65,6172.51 -593.23,6172.51 -574.82,6154.09 -556.4,6172.51 -537.98,6172.51 -556.4,6190.92 -537.98,6209.34 -556.4,6209.34 -574.82,6227.76 -593.23,6209.34 -611.65,6209.34 -593.23,6190.92 -611.65,6172.51 ; -611.65,6319.85 -574.82,6338.27 -537.98,6319.85 -556.4,6356.68 -537.98,6393.52 -574.82,6375.1 -611.65,6393.52 -593.23,6356.68 -611.65,6319.85 ; -596.92,5505.78 -552.72,5505.78 -552.72,5549.98 -596.92,5549.98 -596.92,5505.78 ; -596.92,6047.26 -552.72,6047.26 -574.82,6003.06 -596.92,6047.26 ; -596.92,6179.87 -585.87,6179.87 -574.82,6168.82 -563.77,6179.87 -552.72,6179.87 -563.77,6190.92 -552.72,6201.97 -563.77,6201.97 -574.82,6213.02 -585.87,6201.97 -596.92,6201.97 -585.87,6190.92 -596.92,6179.87 ; -596.92,6334.58 -574.82,6345.63 -552.72,6334.58 -563.77,6356.68 -552.72,6378.78 -574.82,6367.73 -596.92,6378.78 -585.87,6356.68 -596.92,6334.58 ; -554.54,3672.59 4368.53,3672.59 4368.53,4169.87 -554.54,4169.87 -554.54,3672.59 ; -487.23,3906.5 -468.81,3906.5 -468.81,3888.08 -431.98,3888.08 -431.98,3906.5 -413.56,3906.5 -413.56,3943.33 -431.98,3943.33 -431.98,3961.75 -468.81,3961.75 -468.81,3943.33 -487.23,3943.33 -487.23,3906.5 ; -472.5,3913.86 -461.45,3913.86 -461.45,3902.81 -439.35,3902.81 -439.35,3913.86 -428.3,3913.86 -428.3,3935.96 -439.35,3935.96 -439.35,3947.01 -461.45,3947.01 -461.45,3935.96 -472.5,3935.96 -472.5,3913.86
  text "Drill Table: Top Layer to Bottom Layer" at -631.32,6668.77 h80
  text "Symbol" at -579.5,6485.61 h96
  text "Hit Count" at -178.75,6485.61 h96
  text "Finished Hole Size" at 299.79,6485.61 h96
  text "Plated" at 1148.54,6485.61 h96
  text "Hole Type" at 1494.06,6485.61 h96
  text "Physical Length" at 1994.28,6485.61 h96
  text "Rout Path Length" at 2740.46,6485.61 h96
  text "Drill Layer Pair" at 3543.57,6485.61 h96
  text "9" at -178.75,6319.85 h80
  text "7.87mil (0.200mm)" at 299.79,6319.85 h80
  text "PTH" at 1148.54,6319.85 h80
  text "Round" at 1494.06,6319.85 h80
  text "-" at 1994.28,6319.85 h80
  text "-" at 2740.46,6319.85 h80
  text "Top Layer - Bottom Layer" at 3543.57,6319.85 h80
  text "89" at -178.75,6154.09 h80
  text "10.00mil (0.254mm)" at 299.79,6154.09 h80
  text "PTH" at 1148.54,6154.09 h80
  text "Round" at 1494.06,6154.09 h80
  text "-" at 1994.28,6154.09 h80
  text "-" at 2740.46,6154.09 h80
  text "Top Layer - Bottom Layer" at 3543.57,6154.09 h80
  text "340" at -178.75,5988.33 h80
  text "12.20mil (0.310mm)" at 299.79,5988.33 h80
  text "PTH" at 1148.54,5988.33 h80
  text "Round" at 1494.06,5988.33 h80
  text "-" at 1994.28,5988.33 h80
  text "-" at 2740.46,5988.33 h80
  text "Top Layer - Bottom Layer" at 3543.57,5988.33 h80
  text "4" at -178.75,5822.57 h80
  text "40.16mil (1.020mm)" at 299.79,5822.57 h80
  text "NPTH" at 1148.54,5822.57 h80
  text "Round" at 1494.06,5822.57 h80
  text "-" at 1994.28,5822.57 h80
  text "-" at 2740.46,5822.57 h80
  text "Top Layer - Bottom Layer" at 3543.57,5822.57 h80
  text "1" at -178.75,5656.81 h80
  text "80.00mil (2.032mm)" at 299.79,5656.81 h80
  text "PTH" at 1148.54,5656.81 h80
  text "Round" at 1494.06,5656.81 h80
  text "-" at 1994.28,5656.81 h80
  text "-" at 2740.46,5656.81 h80
  text "Top Layer - Bottom Layer" at 3543.57,5656.81 h80
  text "8" at -178.75,5491.05 h80
  text "118.11mil (3.000mm)" at 299.79,5491.05 h80
  text "PTH" at 1148.54,5491.05 h80
  text "Round" at 1494.06,5491.05 h80
  text "-" at 1994.28,5491.05 h80
  text "-" at 2740.46,5491.05 h80
  text "Top Layer - Bottom Layer" at 3543.57,5491.05 h80
  text "451 Total" at -178.75,5325.29 h80
  text "FOR PTH +/- 3MIL" at -673.01,5093.13 h80
  text "FOR NPTH +/- 2MIL" at -675.01,4996.13 h80
  text "FOR 7.874MIL DRILL +0/-7.874MIL" at -677.01,4902.13 h80
  text "FOR 10MIL DRILL +0/-10MIL" at -683.01,4815.13 h80
  text "FOR 12.2MIL DRILL +0/-12.2MIL" at -685.01,4722.13 h80
  text "Drill Table: Layer 1 To Layer 2" at -563.84,4288.68 h80
  text "Symbol" at -455.08,4053.84 h96
  text "Hit Count" at -54.33,4053.84 h96
  text "Finished Hole Size" at 424.21,4053.84 h96
  text "Plated" at 1272.96,4053.84 h96
  text "Hole Type" at 1618.48,4053.84 h96
  text "Physical Length" at 2118.7,4053.84 h96
  text "Rout Path Length" at 2864.88,4053.84 h96
  text "Drill Layer Pair" at 3667.99,4053.84 h96
  text "981" at -54.33,3888.08 h80
  text "5.90mil (0.150mm)" at 424.21,3888.08 h80
  text "PTH" at 1272.96,3888.08 h80
  text "Round" at 1618.48,3888.08 h80
  text "-" at 2118.7,3888.08 h80
  text "-" at 2864.88,3888.08 h80
  text "Top Layer - L2" at 3667.99,3888.08 h80
  text "981 Total" at -54.33,3722.32 h80
  text "FOR 5.9MIL DRILL +0/-5.9MIL" at -534.02,3524.82 h80
  text ".Layer_Name" at -423,-1858.49 h60
M17 Embedded Cavity:
  text ".Layer_Name" at -423,-1858.49 h60
M18 Embedded Assembly:
  text ".Layer_Name" at -423,-1858.49 h60
M19 Embedded Keepout:
  text ".Layer_Name" at -423,-1858.49 h60

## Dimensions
0,2165.35 to 2165.35,2165.35 on Drill Drawing
0,0 to 0,2165.35 on Drill Drawing
-1000,-1400 to 0,-1400 on M2 Board Dimensions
